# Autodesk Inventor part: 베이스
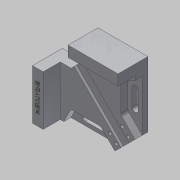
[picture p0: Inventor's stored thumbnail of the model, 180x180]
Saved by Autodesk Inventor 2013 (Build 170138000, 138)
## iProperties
Created: 2019-04
Part Number: 베이스
Material: 알루미늄 6061
Document SubType Name: Modeling
Designer: Administrator
Density: 2.71 g/cm^3
Mass: 603.684 g
Surface Area: 426.592 cm^2
Volume: 222.762 cm^3
Author: Administrator
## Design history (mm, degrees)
sketch "스케치1"
  geometry: L1 (-60, 60)-(60, 60); L2 (60, 60)-(60, -60); L3 (60, -60)-(-60, -60); L4 (-60, -60)-(-60, 60); L5 (-60, 60)-(60, -60); L6 (60, 60)-(-60, -60); 1 further point
  constraints: 12 end point, 2 midpoint, 2 parallel, 1 horizontal, 1 perpendicular
  dimensions: "d0" = 120 distance of L1.start L1.end; "d2" = 120 distance of L1.end L2.end
extrude "돌출1" new body sketch "스케치1" distance "d3" = 18; taper "d4" = 0 deg
sketch "스케치2"
  geometry: L1 (60, 60)-(-60, 60) reference; L2 (60, -60)-(60, 60) reference; L3 (-60, -60)-(-45, -60); L4 (-45, -60)-(-45, 10); L5 (-45, 10)-(-60, 10); L6 (-60, 10)-(-60, -60); L7 (-10, 45)-(60, 45); L8 (60, 45)-(60, 60); L9 (60, 60)-(-10, 60); L10 (-10, 60)-(-10, 45); 1 further point
  constraints: 16 end point, 4 parallel, 2 collinear, 2 horizontal, 2 perpendicular
  dimensions: "d5" = 50 distance between parallel lines of L5 L1; "d6" = 15 distance of L4.end L5.end; "d7" = 50 distance from line of L10 L1.end; "d8" = 15 distance of L7.end L8.end
extrude "돌출2" join sketch "스케치2" distance "d9" = 24; taper "d10" = 0 deg
sketch "스케치3"
  geometry: L1 (-45, -60)-(60, -60) reference; L2 (60, -60)-(60, 45) reference; L3 (-60, 10)-(-60, -60) reference; L4 (-40, -60)-(-30, -40); L5 (-30, -40)-(11.716, -40); L6 (11.716, -40)-(31.716, -60); L7 (-60, 10)-(-45, 10) reference; L8 (60, 40)-(40, 30); L9 (40, 30)-(40, -11.716); L10 (40, -11.716)-(60, -31.716); L11 (60, 60)-(-10, 60) reference; L12 (0, 0)-(60, -60); L13 (-45, 10)-(-45, -60) reference; L14 (-45, -60)-(60, -60) reference; L15 (60, -60)-(60, 45) reference; L16 (60, 45)-(-10, 45) reference; L17 (-10, 45)-(-10, 60) reference; L18 (-10, 60)-(-60, 60) reference; L19 (-60, 60)-(-60, 10) reference; L20 (-60, 10)-(-45, 10) reference
  constraints: 14 end point, 4 point on line, 2 parallel, 2 perpendicular, 1 other
  dimensions: "d13" = 20 distance from line of L4.start L3; "d14" = 30 distance from line of L4.end L3; "d24" = 20 distance from line of L8.start L11; "d28" = 30 vertical distance of L11.start L8.end; "d62" = 20 distance between parallel lines of L1 L5; "d63" = 20 distance between parallel lines of L2 L9; "d66" = 41.716 distance of L4.end L5.end
  node "투영된 루프1"
extrude "돌출3" cut sketch "스케치3" distance "d17" = 10; taper "d18" = 0 deg
sketch "스케치4"
  geometry: L1 (-60, 10)-(-60, -60) reference; L2 (-20, -45.5)-(4, -45.5); L3 (-20, -54.5)-(4, -54.5); L4 (-40, -60)-(-30, -40) reference; L5 (31.716, -60)-(-40, -60) reference; A1 r 4.5 centre (-20, -50) between (-20, -45.5) and (-20, -54.5); A2 r 4.5 centre (4, -50) between (4, -45.5) and (4, -54.5); 2 further points
  constraints: 4 end point, 4 point on circle, 4 tangent, 2 centre point, 2 horizontal alignment, 1 equal radius, 1 midpoint
  dimensions: "d19" = 40 distance from line of A1.centre L1; "d20" = 24 distance of A2.centre A1.centre; "d21" = 9 distance between parallel lines of L3 L2
extrude "돌출4" cut sketch "스케치4" stored distance "d22" = 10; taper "d23" = 0 deg
extrude "돌출5" cut sketch "스케치3" distance "d29" = 10; taper "d30" = 0 deg
sketch "스케치5"
  geometry: L1 (40, 30)-(60, 40) reference; L2 (60, -31.716)-(40, -11.716) reference; L3 (54.5, -4)-(54.5, 20); L4 (45.5, -4)-(45.5, 20); L5 (-60, 60)-(60, 60) reference; L6 (60, 60)-(60, -60) reference; A1 r 4.5 centre (50, -4) between (54.5, -4) and (45.5, -4); A2 r 4.5 centre (50, 20) between (54.5, 20) and (45.5, 20); 3 further points
  constraints: 4 end point, 4 point on circle, 4 tangent, 2 centre point, 2 midpoint, 2 vertical alignment, 1 equal radius
  dimensions: "d32" = 9 diameter of A2; "d34" = 24 distance of A2.centre A1.centre; "d35" = 40 vertical distance of A2.centre L5.end
extrude "돌출6" cut sketch "스케치5" stored distance "d36" = 10; taper "d37" = 0 deg
sketch "스케치6"
  geometry: L1 (-10, 45)-(-10, 60) reference; L2 (-10, 60)-(-60, 60) reference; L3 (-60, 60)-(-60, 10) reference; L4 (-60, 10)-(-45, 10) reference; L5 (31.716, -60)-(60, -60) reference; L6 (60, -60)-(60, -31.716) reference; L7 (40, -11.716)-(40, 30) reference; L8 (-45, 10)-(-29.806, 10); L9 (-10, 10)-(-10, 29.806); L10 (-60, 60)-(60, -60); L11 (31.716, -60)-(60, -31.716); L12 (-29.806, 10)-(-10, 29.806); L13 (-10, 29.806)-(-10, 45); L14 (-29.806, 10)-(-10, 10); L15 (-25.56, 14.246)-(48.686, -60); L16 (-14.246, 25.56)-(60, -48.686); 3 further points
  constraints: 18 end point, 8 perpendicular, 7 point on line, 1 coincident, 1 midpoint, 1 parallel, 1 other
  dimensions: "d45" = 20 distance from line of L5.end L11; "d46" = 93 distance between parallel lines of L12 L11; "d49" = 16 distance between parallel lines of L16 L15
extrude "돌출7" cut sketch "스케치6" stored distance "d47" = 10; taper "d48" = 0 deg
sketch "스케치8"
  geometry: L1 (-10, 45)-(-10, 29.806) reference; L2 (-10, 29.806)-(-29.806, 10) reference; L3 (-29.806, 10)-(-45, 10) reference; L4 (-45, 10)-(-45, -60) reference; L5 (-45, -60)-(-40, -60) reference; L6 (-40, -60)-(-30, -40) reference; L7 (-30, -40)-(11.716, -40) reference; L8 (11.716, -40)-(31.716, -60) reference; L9 (31.716, -60)-(60, -60) reference; L10 (60, -60)-(60, -31.716) reference; L11 (60, -31.716)-(40, -11.716) reference; L12 (40, -11.716)-(40, 30) reference; L13 (40, 30)-(60, 40) reference; L14 (60, 40)-(60, 45) reference; L15 (60, 45)-(-10, 45) reference; 1 further point
sketch "스케치9"
  geometry: L1 (31.716, -60)-(60, -60) reference; L2 (60, -60)-(60, -31.716) reference; L3 (31.716, -60)-(60, -31.716); 1 further point
  constraints: 2 end point, 2 point on line
  dimensions: "d52" = 20 distance from line of L1.end L3; "d53" = 40 distance of L3.start L3.end
extrude "돌출9" cut sketch "스케치9" stored distance "d54" = 3.5; taper "d55" = 0 deg
sketch "스케치10"
  geometry: L1 (29.806, 10)-(10, 29.806) reference; L2 (19.903, 19.903)-(-45.858, -45.858); L3 (15.66, 24.146)-(-50.101, -41.615); L4 (24.146, 15.66)-(-41.615, -50.101); L5 (-41.615, -50.101)-(-50.101, -41.615); L6 (24.146, 15.66)-(15.66, 24.146); 3 further points; 1 other entity
  constraints: 10 end point, 2 point on line, 1 collinear, 1 midpoint, 1 perpendicular, 8 other
  dimensions: "d56" = 12 distance between parallel lines of L4 L3
extrude "돌출10" cut sketch "스케치10" distance "d58" = 3; taper "d59" = 0 deg
extrude "돌출11" cut sketch "스케치6" distance "d60" = 3.5; taper "d61" = 0 deg
sketch "스케치12"
  geometry: L1 (-50.101, -41.615)-(15.66, 24.146) reference; L2 (-60, -31.716)-(-50.101, -41.615) reference; 3 further points
  dimensions: "d67" = 6 distance from line of L1 point (-50.101, -33.13); "d68" = 6 distance from line of L1 point (-41.615, -24.645); "d69" = 6 distance from line of L2 point (-50.101, -33.13); "d70" = 12 distance of point (-41.615, -24.645) point (-50.101, -33.13)
hole "구멍1" sketch "스케치12" at (-50.101, -33.13), (-41.615, -24.645) diameter "d71" = 4.5; stored, may be unused: countersink angle "d75" = 90 deg, drill point angle "d77" = 118 deg; dims "d72" = 6, "d73" = 8, "d74" = 10, "d76" = 8
sketch "스케치13"
  geometry: L1 (24.146, 15.66)-(-41.615, -50.101) reference; L2 (-41.615, -50.101)-(-31.716, -60) reference; 3 further points
  dimensions: "d78" = 6 distance from line of point (-33.13, -50.101) L1; "d79" = 6 distance from line of point (-24.645, -41.615) L1; "d80" = 6 distance from line of point (-33.13, -50.101) L2; "d81" = 12 distance of point (-24.645, -41.615) point (-33.13, -50.101)
hole "구멍2" sketch "스케치13" at (-33.13, -50.101), (-24.645, -41.615) diameter "d82" = 4.5; stored, may be unused: countersink angle "d86" = 90 deg, drill point angle "d88" = 118 deg; dims "d83" = 6, "d84" = 8, "d85" = 10, "d87" = 8
sketch "스케치14"
  geometry: L1 (-45, -60)-(-45, 10) reference; L2 (-45, 10)-(-60, 10) reference; 2 further points
  constraints: 1 other
  dimensions: "d89" = 35 distance from line of point (-52.5, -25) L2; "d90" = 7.5 distance from line of L1 point (-52.5, -25)
feature "엠보싱1" sketch "스케치14" dims "d0" = 120, "d2" = 120, "d91" = 0.5, "d92" = 0
fillet "모깎기1" dims "d93" = 5
extrude "돌출8" cut sketch "스케치6" distance "d50" = 3.5; taper "d51" = 0 deg
node "솔리드1"
